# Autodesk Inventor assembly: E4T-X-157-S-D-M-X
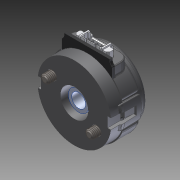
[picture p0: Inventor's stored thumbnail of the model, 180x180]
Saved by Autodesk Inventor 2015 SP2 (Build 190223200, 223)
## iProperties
Created: 2016-05
Part Number: E4T-X-157-S-D-M-X
Document SubType Name: Assembly
Designer: ryll
Author: ryll
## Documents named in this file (8)
- D:\TIGERs GIT\Hardware\mechanik\2016\Inventor\Kaufteile\E4T-X-157-S-D-M-X\E4T-X-157-S-D-M-X.iam
- D:\TIGERs GIT\Hardware\mechanik\2016\Inventor\Kaufteile\E4T-X-157-S-D-M-X\E4T-X-157-S-D-M-X.ipt
- D:\TIGERs GIT\Hardware\mechanik\2016\Inventor\Kaufteile\E4T-X-157-S-D-M-X\E4T-X-157-S-D-M-X_1.ipt
- D:\TIGERs GIT\Hardware\mechanik\2016\Inventor\Kaufteile\E4T-X-157-S-D-M-X\E4T-X-157-S-D-M-X_2.ipt
- D:\TIGERs GIT\Hardware\mechanik\2016\Inventor\Kaufteile\E4T-X-157-S-D-M-X\E4T-X-157-S-D-M-X_3.ipt
- D:\TIGERs GIT\Hardware\mechanik\2016\Inventor\Kaufteile\E4T-X-157-S-D-M-X\E4T-X-157-S-D-M-X_4.ipt
- D:\TIGERs GIT\Hardware\mechanik\2016\Inventor\Kaufteile\E4T-X-157-S-D-M-X\E4T-X-157-S-D-M-X_5.ipt
- D:\TIGERs GIT\Hardware\mechanik\2016\Inventor\Kaufteile\E4T-X-157-S-D-M-X\E4T-X-157-S-D-M-X_6.ipt
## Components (7 placed, 7 different names)
1. E4T-X-157-S-D-M-X:1
2. E4T-X-157-S-D-M-X_1:1
3. E4T-X-157-S-D-M-X_2:1
4. E4T-X-157-S-D-M-X_3:1
5. E4T-X-157-S-D-M-X_4:1
6. E4T-X-157-S-D-M-X_5:1
7. E4T-X-157-S-D-M-X_6:1
